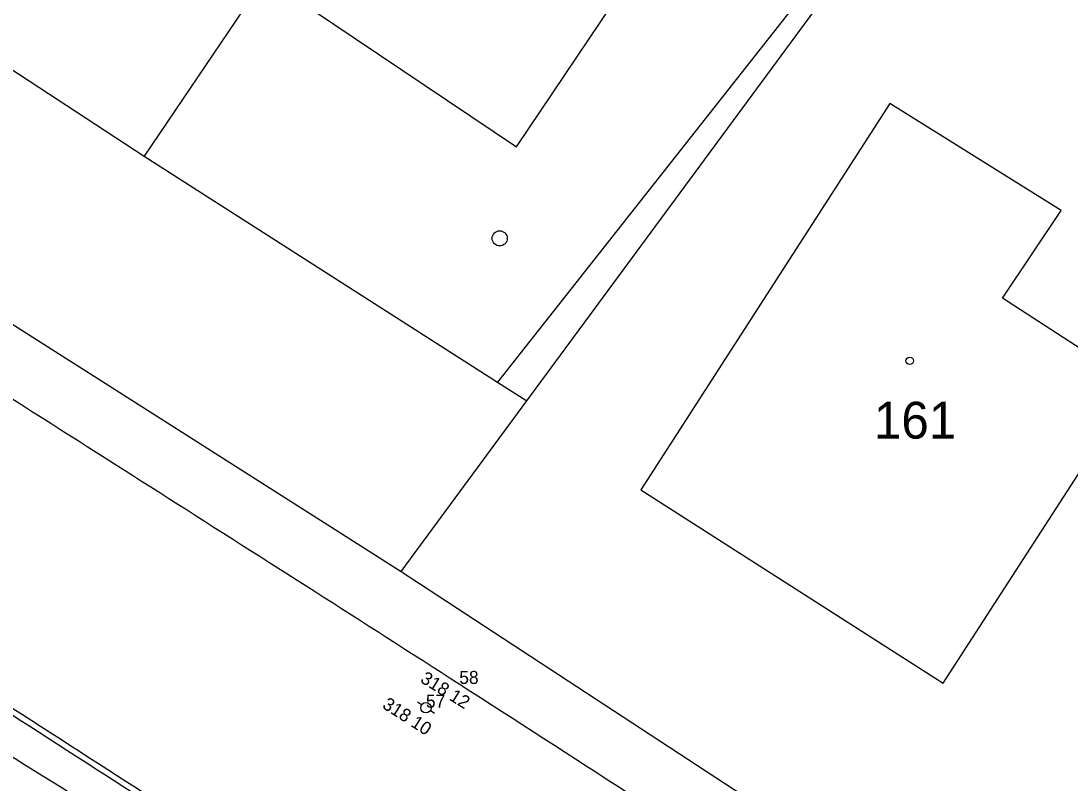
# Model space of a CAD drawing. Extents: x -742884 to -742543, y -1054677 to -1054433.
# Drawn here: x -742706.11 to -742681.87, y -1054495.74 to -1054478.13 of the extents above; entities that cross this region are included whole.
import ezdxf

# ---------------------------------------------------------------- set-up
doc = ezdxf.new("R2010")
doc.units = 0
for name, color, linetype in [('Vrstva 1', 7, 'Continuous'), ('Vrstva 11', 7, 'Continuous'), ('Vrstva 13', 7, 'Continuous'), ('Vrstva 2', 7, 'Continuous'), ('Vrstva 3', 7, 'Continuous'), ('Vrstva 4', 7, 'Continuous'), ('Vrstva 50', 7, 'Continuous'), ('Vrstva 8', 7, 'Continuous')]:
    doc.layers.add(name, color=color, linetype=linetype)

msp = doc.modelspace()

# ---------------------------------------------------------------- linework, layer by layer
at = {"layer": 'Vrstva 1'}
for p, q in [((-742695.99, -1054493.43), (-742695.99, -1054493.43)), ((-742696.76, -1054493.98), (-742696.76, -1054493.98))]:
    msp.add_line(p, q, dxfattribs=at)
at = {"layer": 'Vrstva 11'}
msp.add_spline([(-742776.7, -1054542.68), (-742764.01, -1054527.79), (-742751.11, -1054512.75), (-742737.61, -1054496.47), (-742726.42, -1054483.98), (-742725.9, -1054484.03), (-742714, -1054491.86), (-742704.819, -1054497.481), (-742700.94, -1054500.269), (-742696.44, -1054503.39), (-742688.83, -1054509.5), (-742682.54, -1054514.17), (-742675.15, -1054519.77), (-742673.01, -1054522.11), (-742671.05, -1054524.7)], degree=3, dxfattribs=at)
at = {"layer": 'Vrstva 13'}
msp.add_spline([(-742725.15, -1054482.94), (-742713.48, -1054490.62), (-742699.44, -1054499.41), (-742696.97, -1054500.991)], degree=3, dxfattribs=at)
at = {"layer": 'Vrstva 4'}
for points in [[(-742718.8, -1054478.84), (-742709.4, -1054484.88), (-742695.99, -1054493.43), (-742680.4, -1054503.55), (-742661.01, -1054516), (-742635.78, -1054532.31)], [(-742668.427, -1054518.574), (-742683.74, -1054508.68), (-742696.59, -1054500.4), (-742699.13, -1054498.77), (-742713.15, -1054489.73), (-742724.623, -1054482.289)], [(-742668.31, -1054518.5), (-742683.67, -1054508.57), (-742699.06, -1054498.66), (-742713.08, -1054489.62), (-742724.57, -1054482.17)]]:
    msp.add_spline(points, degree=3, dxfattribs=at)
at = {"layer": 'Vrstva 50'}
for p, q in [((-742683.39, -1054471.6), (-742695.11, -1054486.47)), ((-742694.43, -1054486.9), (-742683.25, -1054471.72)), ((-742700.48, -1054477.13), (-742703.26, -1054481.25)), ((-742697.33, -1054490.84), (-742694.43, -1054486.9)), ((-742697.33, -1054490.84), (-742680.73, -1054501.69))]:
    msp.add_line(p, q, dxfattribs=at)
for points in [[(-742709.25, -1054467.41), (-742705.82, -1054469.13), (-742710.59, -1054476.45), (-742703.26, -1054481.25), (-742695.11, -1054486.47), (-742694.43, -1054486.9)], [(-742700.48, -1054477.13), (-742694.67, -1054481.04), (-742686.55, -1054468.97)], [(-742717.19, -1054476.37), (-742717.22, -1054478.19), (-742697.33, -1054490.84)], [(-742680.37, -1054486.53), (-742683.45, -1054484.53), (-742682.1, -1054482.51), (-742686.05, -1054480.04), (-742691.8, -1054488.95), (-742684.82, -1054493.41), (-742680.37, -1054486.53)]]:
    msp.add_lwpolyline(points, dxfattribs=at)
for centre, radius in [((-742695.057, -1054483.149), 0.175), ((-742685.593, -1054485.975), 0.0875)]:
    msp.add_circle(centre, radius, dxfattribs=at)
at = {"layer": 'Vrstva 8'}
for p, q in [((-742696.861, -1054493.914), (-742696.957, -1054493.851)), ((-742696.559, -1054494.112), (-742696.658, -1054494.047))]:
    msp.add_line(p, q, dxfattribs=at)
msp.add_circle((-742696.76, -1054493.98), 0.121, dxfattribs=at)

# ---------------------------------------------------------------- texts
at = {"layer": 'Vrstva 2'}
for s, p in [('58', (-742695.99, -1054493.43)), ('57', (-742696.76, -1054493.98))]:
    msp.add_text(s, height=0.3, dxfattribs=at).set_placement(p)
at = {"layer": 'Vrstva 3'}
for s, rotation, p in [('318 12 ', 328.3925, (-742696.909, -1054493.377)), ('318 10 ', 327.3985, (-742697.788, -1054493.972))]:
    msp.add_text(s, height=0.3, rotation=rotation, dxfattribs=at).set_placement(p)
at = {"layer": 'Vrstva 50'}
msp.add_text('161', height=0.85, dxfattribs=at).set_placement((-742686.418, -1054487.77))

doc.saveas('drawing.dxf')
